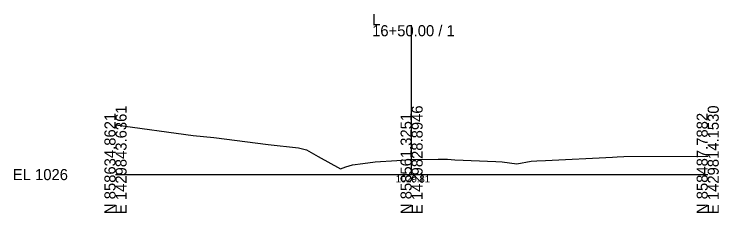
# Model space of a CAD drawing. Extents: x -26 to 176, y -10 to 13058.
# Drawn here: x -25.7 to 152.8, y 9990.3 to 10040.6 of the extents above; entities that cross this region are included whole.
import ezdxf

# ---------------------------------------------------------------- set-up
doc = ezdxf.new("R2010")
doc.units = 0
for name, color, linetype in [('Default', 7, 'Continuous'), ('Exist Cross Section Cell', 7, 'Continuous'), ('Exist XS Center Line Elevation Label', 7, 'Continuous'), ('Exist XS Ground Line', 7, 'Continuous')]:
    doc.layers.add(name, color=color, linetype=linetype)

msp = doc.modelspace()

# ---------------------------------------------------------------- linework, layer by layer
at = {"layer": 'Exist Cross Section Cell'}
for p, q in [((75, 10000), (75, 10037.79)), ((0, 10000), (75, 10000)), ((75, 10000), (150, 10000))]:
    msp.add_line(p, q, dxfattribs=at)
at = {"layer": 'Exist XS Ground Line'}
msp.add_lwpolyline([(0, 10012.6), (19.63, 10009.92), (24.9, 10009.37), (38.63, 10007.6), (46.38, 10006.75), (48.35, 10006.28), (51.34, 10004.54), (56.95, 10001.49), (58.32, 10001.93), (60.04, 10002.43), (62.68, 10002.79), (65.78, 10003.26), (71.22, 10003.6), (74.64, 10003.81), (75, 10003.81), (81.74, 10003.87), (84.13, 10003.9), (85.98, 10003.71), (96.32, 10003.31), (97.95, 10003.24), (101.65, 10002.7), (105.25, 10003.39), (106.76, 10003.45), (108.9, 10003.58), (125.88, 10004.44), (127.07, 10004.5), (128.79, 10004.55), (149.63, 10004.64), (150, 10004.65)], dxfattribs=at)

# ---------------------------------------------------------------- texts
at = {"layer": 'Default'}
msp.add_text('-', height=0.0001, dxfattribs=at).set_placement((0, 10000))
at = {"layer": 'Exist Cross Section Cell'}
for s, p in [('L', (65, 10037.79)), ('16+50.00 / 1', (65, 10034.99)), ('EL 1026', (-26, 9998.6))]:
    msp.add_text(s, height=2.8, dxfattribs=at).set_placement(p)
for s, p in [('E 1429843.6361', (2.8, 9990)), ('E 1429828.8946', (77.8, 9990)), ('E 1429814.1530', (152.8, 9990)), ('N 858634.8621', (0, 9990)), ('N 858561.3251', (75, 9990)), ('N 858487.7882', (150, 9990))]:
    msp.add_text(s, height=2.8, rotation=90, dxfattribs=at).set_placement(p)
at = {"layer": 'Exist XS Center Line Elevation Label'}
msp.add_text('1029.81', height=1.8, dxfattribs=at).set_placement((70.97, 9998.01))
msp.add_text('1029.81', height=1.8, dxfattribs=at).set_placement((70.97, 9998.01))
msp.add_text('1029.81', height=1.8, dxfattribs=at).set_placement((70.97, 9998.01))

doc.saveas('drawing.dxf')
